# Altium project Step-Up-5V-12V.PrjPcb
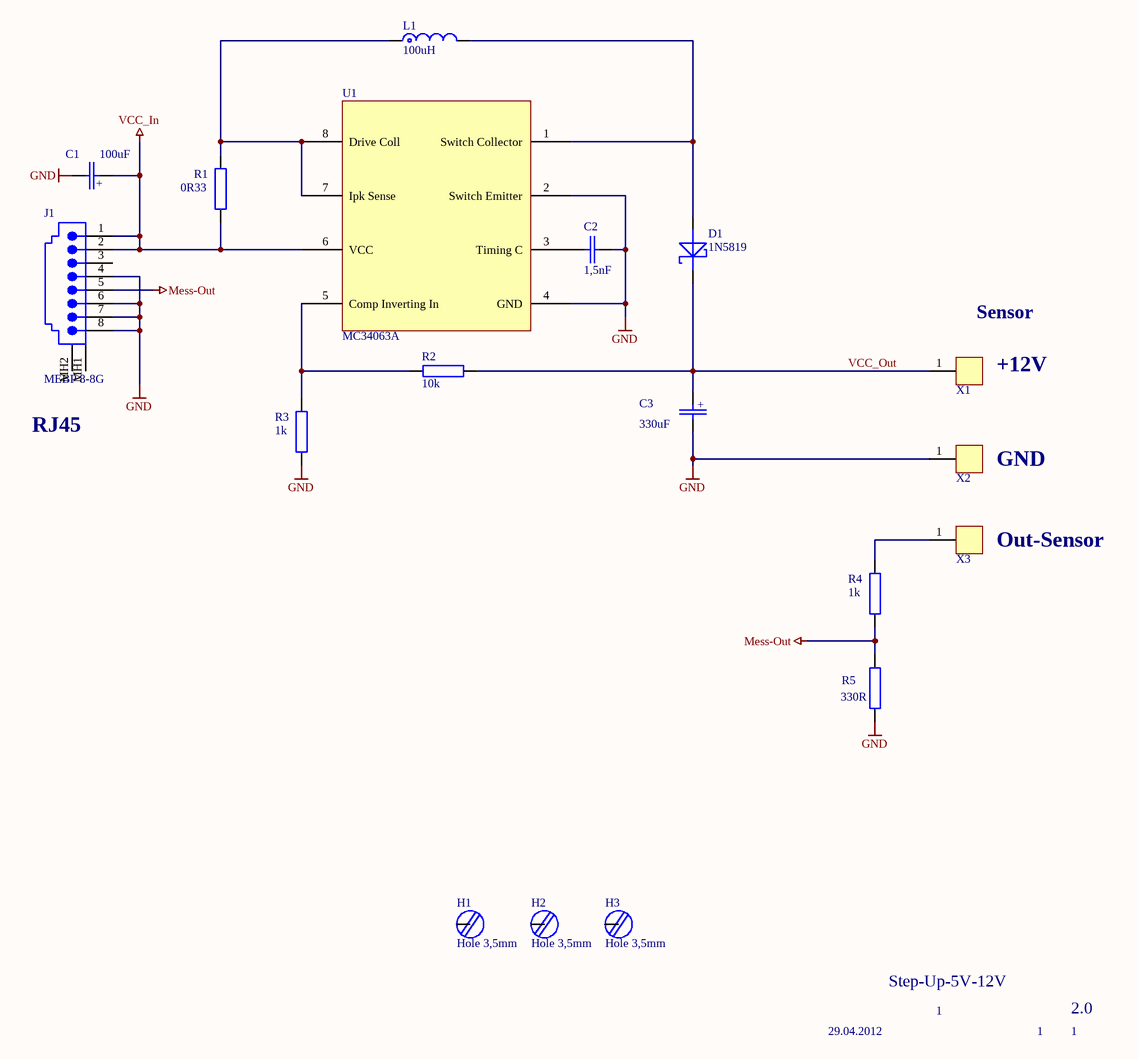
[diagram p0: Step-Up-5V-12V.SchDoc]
1 sheet, 18 parts. Net scope: global (net labels, ports and power ports of the same name join across sheets).
Board file: Step-Up-5V-12V.PcbDoc

## Sheet Step-Up-5V-12V.SchDoc
size A3; Organization: Altium Limited; Address1: MK; PageSetup: Record=PageOptions|CenterHorizontal=True|CenterVertical=True|PrintScale=0.69|XCorrection=1.00|YCorrection=1.00|PrintKind=2|BorderSize=5000000|LeftOffset=0|BottomOffset=0|Orientation=2|PaperLength=1000|PaperWidth=1000|Scale=100|PaperSource=7|PrintQuality=-4|MediaType=1|DitherType=10|PaperKind=A4|PrintScaleMode=1

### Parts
C1  100uF  [CAPMP7343X31M]
C2  1,5nF  [CAPC2012X09M]
C3  330uF  [ELK_RM020_5x11]
D1  1N5819  [DO-201]
H1  Hole 3,5mm  [M3+SCHEIBE]
H2  Hole 3,5mm  [M3+SCHEIBE]
H3  Hole 3,5mm  [M3+SCHEIBE]
J1  MEBP 8-8G  [RJ45-JACK-MEBP 8-8G]
L1  100uH  [INDM127100X52M]
R1  0R33  [RESC3216X06M]
R2  10k  [RESC3216X06M]
R3  1k  [RESC3216X06M]
R4  1k  [RESC3216X06M]
R5  330R  [RESC3216X06M]
U1  MC34063A  [SO-8]
X1  Ground  [GND_PAD3]  (value not drawn)
X2  Ground  [GND_PAD3]  (value not drawn)
X3  Ground  [GND_PAD3]  (value not drawn)

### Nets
GND: C1.2 C2.2 C3.2 J1.4 J1.6 J1.7 J1.8 R3.2 R5.1 U1.2(Switch_Emitter) U1.4(GND) X2.1
Mess-Out: J1.5 R4.2 R5.2
VCC_In: C1.1 J1.1 J1.2 R1.2 U1.6(VCC)
VCC_Out: C3.1 D1.K(CATHODE) R2.1 X1.1
NetC2_1: C2.1 U1.3(Timing_C)
NetD1_A: D1.A(ANODE) L1.2 U1.1(Switch_Collector)
NetL1_1: L1.1 R1.1 U1.7(Ipk_Sense) U1.8(Drive_Coll)
NetR2_2: R2.2 R3.1 U1.5(Comp_Inverting_In)
NetR4_1: R4.1 X3.1

Not connected (* = marked no-connect by the designer): H1 1; H2 1; H3 1; J1 3 MH1(Shield) MH2(Shield)

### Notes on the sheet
- (near X1) Sensor
- RJ45
- (near X1) +12V
- (near X2) GND
- (near X3) Out-Sensor
- 29.04.2012
- Step-Up-5V-12V
- 1
- 2.0

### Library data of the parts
C1 = 33UF_6032: Capacitor Tantalum Case D; Manufacturer: AVX; Part No.: 197671; Tolerance: 10%; Class: passive; Voltage: 35V; Note: RoHS konf. /; SAP No.: 6507 2093; Value: 33uF; Herst. Bezeichnung: TAJD336K035R
C2 = 1,5NF_0805: Capacitor X7R SMD; Manufacturer: PHYCOMP; Part No.: 3019883RL; Tolerance: 10%; Class: passive; Voltage: 50V; Note: RoHS konf. /; Herst. Bezeichnung: 2238 580 15625
C3 = 100UF_RM2.0_16V: Capacitor Aluminum Electrolytic 16V 100uF; Manufacturer: Vishay; Part No.: 684-1905; Tolerance: 20%; Class: passive; Voltage: 50V; Note: RoHS konf. / Low Impedance; Herst. Bezeichnung: MAL203855101E3
D1 = 1N5822_DO-201: Schottkydiode 3A/40V; Part No.: 7429339; Manufacturer: MULTICOMP; Voltage: 40V; Current: 3A; SAP No.: 6506 2346; Class: passiv; Note: RoHS konf. /; SubClass: Schottky-Diode; Value: 1N5822
H1-H3 = HOLE_3_5: Bohrung 3.5mm; Class: passive; SubClass: mechanic
J1 = RJ45-JACK-MEBP 8-8G: Right Angle, Standard Profile, External Shield PCB Jack; Class: passive; Note: RoHS konf. / MEBP 8-8G; SubClass: Connector
L1 = WE-PD-3-L_10uH: SMD Shielded Power Inductor WE-PD3, L=10.0 µH; Manufacturer: Würth; Part No.: 1636087; Class: passive; Note: RoHS konf.; Current: 2A; Tolerance: 20%; Value: 10uH; Herst. Bezeichnung: 74454010
R1 = 0R33_1206: SMD Resistor; Manufacturer: Yageo; Part No.: 08 E 136; Power: 0,25W; Tolerance: 1%; Class: passive; Note: RoHS konf.
R2 = 10K_1206: SMD Resistor; Part No.: 0236 10K; Power: 0,25W; Voltage: 200 V; SAP No.: 6507 4271; Tolerance: 1%; Class: passive; Note: RoHS konf.
R3 R4 = 1K_1206: SMD Resistor; Part No.: 0236 1K; Power: 0,25W; Voltage: 200 V; SAP No.: 6507 4246; Tolerance: 1%; Class: passive; Note: RoHS konf.
R5 = 330R_1206: SMD Resistor; Manufacturer: PHYCOMP; Part No.: 9240918; Power: 0,25W; Voltage: 200 V; Tolerance: 1%; Class: passive; Note: RoHS konf. /; Herst. Bezeichnung: 232272463301
X1-X3 = GND_PAD3: Groundpad; Class: passive; SubClass: mechanic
